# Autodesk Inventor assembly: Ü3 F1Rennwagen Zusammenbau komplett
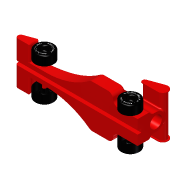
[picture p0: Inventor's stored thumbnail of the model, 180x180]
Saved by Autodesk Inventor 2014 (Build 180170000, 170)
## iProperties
Created: 2013-07
Part Number: Ü3 F1Rennwagen Zusammenbau komplett
Document SubType Name: Assembly
Designer: Sofia
Author: Sofia
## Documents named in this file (5)
- C:\F1 in Schools\Workspace\Ü3 F1Rennwagen Zusammenbau komplett.iam
- C:\F1 in Schools\Workspace\F1 Karosserie komplett.ipt
- C:\F1 in Schools\Workspace\Rad.ipt
- C:\F1 in Schools\Workspace\Sicherungsring.ipt
- C:\F1 in Schools\Workspace\Achse.ipt
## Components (9 placed, 4 different names)
1. F1 Karosserie komplett:1 — Passend:1, Passend:2, Einfügen:1, Passend:3, Passend:4
2. Achse:1 — Einfügen:2, Passend:3, Einfügen:3
3. Sicherungsring:1 — Einfügen:2, Einfügen:4
4. Rad:1 — Passend:1, Passend:2, Einfügen:3
5. Achse:2 — Passend:4, Einfügen:5, Einfügen:6
6. Sicherungsring:2 — Einfügen:6, Einfügen:7
7. Rad:2 — Einfügen:7
8. Rad:3 — Einfügen:4
9. Rad:4 — Einfügen:1, Einfügen:5
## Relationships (11: Insert 7, Mate 4)
- Passend:1 [Mate]: F1 Karosserie komplett:1 ↔ Rad:1
- Passend:2 [Mate]: F1 Karosserie komplett:1 ↔ Rad:1
- Einfügen:1 [Insert]: F1 Karosserie komplett:1 ↔ Rad:4
- Einfügen:2 [Insert]: Achse:1 ↔ Sicherungsring:1
- Passend:3 [Mate]: F1 Karosserie komplett:1 ↔ Achse:1
- Einfügen:3 [Insert]: Achse:1 ↔ Rad:1
- Einfügen:4 [Insert]: Sicherungsring:1 ↔ Rad:3
- Passend:4 [Mate]: F1 Karosserie komplett:1 ↔ Achse:2
- Einfügen:5 [Insert]: Achse:2 ↔ Rad:4
- Einfügen:6 [Insert]: Achse:2 ↔ Sicherungsring:2
- Einfügen:7 [Insert]: Sicherungsring:2 ↔ Rad:2
